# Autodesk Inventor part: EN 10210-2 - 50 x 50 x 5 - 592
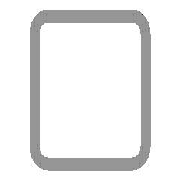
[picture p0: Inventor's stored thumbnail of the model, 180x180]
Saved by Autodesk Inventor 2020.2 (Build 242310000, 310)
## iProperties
IsCustomPart: 1
Created: 2019-01
Part Number: EN 10210-2 - 50 x 50 x 5 - 592
Material: Stahl, weich
Description: Rohrleitung
Document SubType Name: Modeling
Standard: DIN
Designer: lutzd
Standard Revision: 2006-07
Standards Organization: DIN
Language: de-DE
Size Designation: 50 x 50 x 5
Categories: <MemberInstance><Categories><Category DisplayName="Profile" InternalName="089c4875-fa83-4c05-b084-43b9cc11f5ed" Mnemonic="GRDR"><CategoryParameter DisplayName="
Stock Number: 50 x 50 x 5
Mass: 4055.09 g
Surface Area: 2022.32 cm^2
Volume: 516.572 cm^3
Density: 7.85 g/cm^3
Appearance: Semi-Polished(8)
G_L: 592,000 mm
G_W: 50,000 mm
G_H: 50,000 mm
DocNumber: ADSK-014279
Folder: .
Dimensions: 50x50x592 mm
Mass: 4,055 kg
+FC4613A7-7A18-4C67-8E0D-19F2ED57CA28+SCHNITTDETAIL1: Schnittwinkel 90,00 grd
+DF4456C8-933E-4386-8037-BC8AB9D58146+SCHNITTDETAIL2: Schnittwinkel 90,00 grd
VLT_Material: Stahl, weich
_CCFamilyMember: 16
_CCFamilyDisplayName: DIN EN 10210-2 (USAS B17.1 quadratisch) - Rohrleitung — In Klammern angegebene Größen wurden aufgehoben
_FrameMemberDoc: Frame Member File
_Version: 15.0.0
_GetPNFromCC: 1
Title: Profil-Bauteil
Author: lutzd
Revision Number: -
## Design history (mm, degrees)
node "Startebene"
node "Endebene"
sketch "Skizze"
  geometry: L1 (-25, -17.5)-(-25, 17.5); L2 (-17.5, 25)-(17.5, 25); L3 (25, 17.5)-(25, -17.5); L4 (17.5, -25)-(-17.5, -25); L5 (-15, 20)-(15, 20); L6 (20, 15)-(20, -15); L7 (15, -20)-(-15, -20); L8 (-20, -15)-(-20, 15); L9 (0, 37.175)-(0, -37.175) reference; L10 (-37.175, 0)-(37.175, 0) reference; A1 r 7.5 centre (-17.5, -17.5) between (-25, -17.5) and (-17.5, -25); A2 r 7.5 centre (-17.5, 17.5) between (-17.5, 25) and (-25, 17.5); A3 r 7.5 centre (17.5, 17.5) between (25, 17.5) and (17.5, 25); A4 r 7.5 centre (17.5, -17.5) between (17.5, -25) and (25, -17.5); A5 r 5 centre (-15, -15) between (-20, -15) and (-15, -20); A6 r 5 centre (-15, 15) between (-15, 20) and (-20, 15); A7 r 5 centre (15, 15) between (20, 15) and (15, 20); A8 r 5 centre (15, -15) between (15, -20) and (20, -15)
  constraints: 16 end point, 16 point on circle, 16 tangent, 8 centre point, 6 equal radius, 4 parallel, 2 perpendicular, 2 other
  dimensions: "d7" = 7.5 radius of A1 (= G_IR); "d10" = 50 distance between parallel lines of L2 L4 (= G_H); "d11" = 50 distance between parallel lines of L1 L3 (= G_W); "d12" = 5 distance between parallel lines of L3 L6 (= G_T); "d15" = 25 distance between parallel lines of L2 L10 (= 0.5 x d10); "d16" = 25 distance between parallel lines of L9 L3 (= 0.5 x d11); "d19" = 5 radius of A5 (= G_T); "d20" = 5 distance between parallel lines of L4 L7 (= G_T)
extrude "Körper" new body sketch "Skizze" stored distance "d3" = 592 (= G_L); taper "d4" = 0 deg
node "Driven Length"
  sketch "Sketch3"
    geometry: L1 (0, 0)-(10, 0) reference
    constraints: 2 end point, 1 horizontal
  workplane "Work Plane3"
  sketch "Sketch4"
    geometry: L1 (-2, 25)-(12, 25) reference; L2 (-2, 617)-(12, 617) reference
    dimensions: "d18" = 592 distance between parallel lines of L1 L2 (derived)
workplane "Arbeitsebene4"
feature "Trennen1"
workplane "Arbeitsebene5"
feature "Trennen2"
sketch "Skizze5"
  geometry: L1 (35, 592)-(0, 592) reference; L2 (17.5, 592)-(17.5, 493); 3 further points
  constraints: 2 end point, 1 coincident, 1 midpoint, 1 point on line, 1 vertical
  dimensions: "d21" = 9 distance from line of point (17.5, 583) L1; "d22" = 90 distance of point (17.5, 493) point (17.5, 583)
hole "Bohrung1" sketch "Skizze5" at (17.5, 583), (17.5, 493) diameter "d23" = 6.647; stored, may be unused: countersink angle "d27" = 90 deg, drill point angle "d29" = 118 deg; dims "d24" = 16, "d25" = 4, "d26" = 2, "d28" = 22.2
body "Solid1"
other parameters: "G_W" = 50 [user parameter; used in 1 equation term], "G_H" = 50 [user parameter; used in 1 equation term], "G_T" = 5 [user parameter; used in 3 equation terms], "G_IR" = 7.5 [user parameter; used in 1 equation term], "G_L" = 592 (= d18) [user parameter; used in 1 equation term], "G_OFFSET_START" = -25 [user parameter; used in 1 equation term], "d13" = 25 (= -G_OFFSET_START), "d14" = 617 (= G_OFFSET_END + B_L), "B_L" = 667 [user parameter; used in 1 equation term], "d17" = 90 deg
